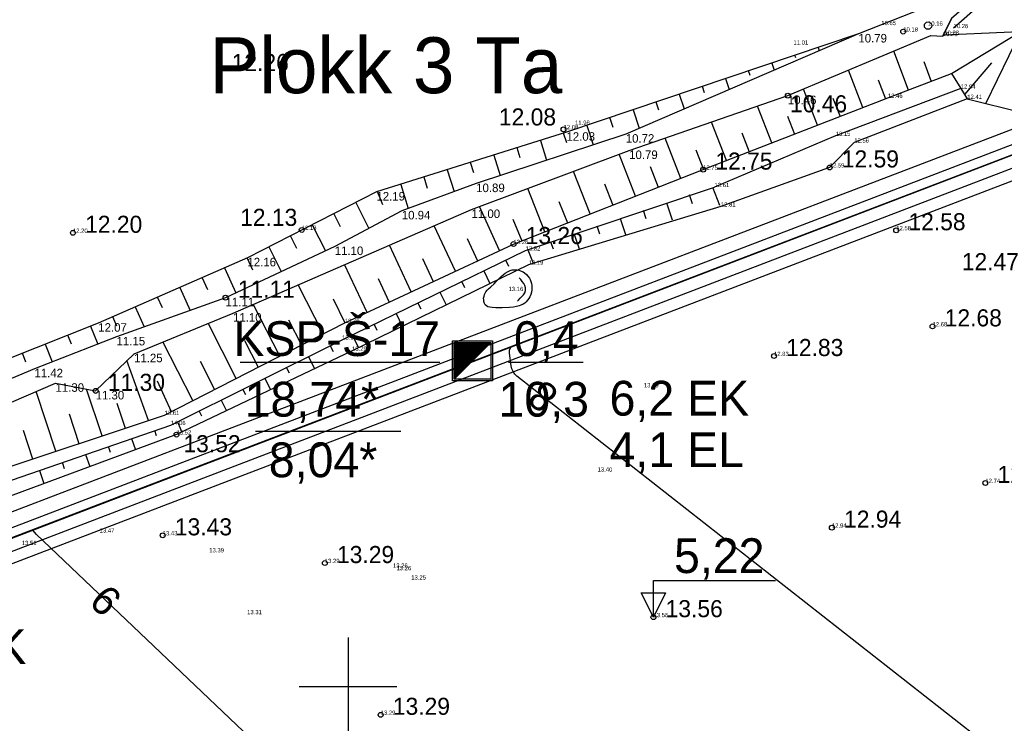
# Model space of a CAD drawing. Extents: x 433497 to 434382, y 6534486 to 6534993.
# Drawn here: x 433673.1 to 433753.8, y 6534797 to 6534854.6 of the extents above; entities that cross this region are included whole.
import ezdxf

# ---------------------------------------------------------------- set-up
doc = ezdxf.new("R2010")
doc.units = 0
for name, color, linetype in [('Default', 7, 'Continuous'), ('GEOLPUNKT', 7, 'Continuous'), ('jääkpaksus', 7, 'Continuous'), ('kataster', 7, 'Continuous'), ('KORGUS-EH2000', 7, 'Continuous'), ('Lamami horisontaal', 7, 'Continuous'), ('MOOTKORG-EH2000', 7, 'Continuous'), ('PIIR', 7, 'Continuous'), ('RELJEEF', 7, 'Continuous'), ('VEEKOGU', 7, 'Continuous'), ('VORK', 7, 'Continuous')]:
    doc.layers.add(name, color=color, linetype=linetype)

msp = doc.modelspace()

# ---------------------------------------------------------------- linework, layer by layer
at = {"layer": 'Default'}
msp.add_lwpolyline([(433617.12, 6534791.025), (433632.75, 6534606.045), (434137.38, 6534796.515), (434127.69, 6534855.6), (433968.21, 6534911.925), (433942.38, 6534904.035), (433920.99, 6534907.275)], close=True, dxfattribs=at)
msp.add_lwpolyline([(433617.12, 6534791.025), (433632.75, 6534606.045), (434137.38, 6534796.515), (434127.69, 6534855.6), (433968.21, 6534911.925), (433942.38, 6534904.035), (433920.99, 6534907.275)], close=True, dxfattribs=at)
msp.add_lwpolyline([(433617.12, 6534791.025), (433632.75, 6534606.045), (434137.38, 6534796.515), (434127.69, 6534855.6), (433968.21, 6534911.925), (433942.38, 6534904.035), (433920.99, 6534907.275)], close=True, dxfattribs=at)
at = {"layer": 'GEOLPUNKT'}
for p, q in [((433708.715, 6534825.184), (433711.715, 6534828.184)), ((433708.715, 6534825.215), (433711.685, 6534828.184)), ((433708.715, 6534825.285), (433711.614, 6534828.184)), ((433708.715, 6534825.356), (433711.543, 6534828.184)), ((433708.715, 6534825.427), (433711.472, 6534828.184)), ((433708.715, 6534825.497), (433711.402, 6534828.184)), ((433708.715, 6534825.568), (433711.331, 6534828.184)), ((433708.715, 6534825.639), (433711.26, 6534828.184)), ((433708.715, 6534825.71), (433711.19, 6534828.184)), ((433708.715, 6534825.78), (433711.119, 6534828.184)), ((433708.715, 6534825.851), (433711.048, 6534828.184)), ((433708.715, 6534825.922), (433710.977, 6534828.184)), ((433708.715, 6534825.992), (433710.907, 6534828.184)), ((433708.715, 6534826.063), (433710.836, 6534828.184)), ((433708.715, 6534826.134), (433710.765, 6534828.184)), ((433708.715, 6534826.205), (433710.695, 6534828.184)), ((433708.715, 6534826.275), (433710.624, 6534828.184)), ((433708.715, 6534826.346), (433710.553, 6534828.184)), ((433708.715, 6534826.417), (433710.482, 6534828.184)), ((433708.715, 6534826.487), (433710.412, 6534828.184)), ((433708.715, 6534826.558), (433710.341, 6534828.184)), ((433708.715, 6534826.629), (433710.27, 6534828.184)), ((433708.715, 6534826.699), (433710.2, 6534828.184)), ((433708.715, 6534826.77), (433710.129, 6534828.184)), ((433708.715, 6534826.841), (433710.058, 6534828.184)), ((433708.715, 6534826.912), (433709.987, 6534828.184)), ((433708.715, 6534826.982), (433709.917, 6534828.184)), ((433708.715, 6534827.053), (433709.846, 6534828.184)), ((433708.715, 6534827.124), (433709.775, 6534828.184)), ((433708.715, 6534827.194), (433709.705, 6534828.184)), ((433708.715, 6534827.265), (433709.634, 6534828.184)), ((433708.715, 6534827.336), (433709.563, 6534828.184)), ((433708.715, 6534827.407), (433709.493, 6534828.184)), ((433708.715, 6534827.477), (433709.422, 6534828.184)), ((433708.715, 6534827.548), (433709.351, 6534828.184)), ((433708.715, 6534827.619), (433709.28, 6534828.184)), ((433708.715, 6534827.689), (433709.21, 6534828.184)), ((433708.715, 6534827.76), (433709.139, 6534828.184)), ((433708.715, 6534827.831), (433709.068, 6534828.184)), ((433708.715, 6534827.902), (433708.998, 6534828.184)), ((433708.715, 6534827.972), (433708.927, 6534828.184)), ((433708.715, 6534828.043), (433708.856, 6534828.184)), ((433708.715, 6534828.114), (433708.785, 6534828.184)), ((433710.215, 6534826.684), (433710.215, 6534826.684))]:
    msp.add_line(p, q, dxfattribs=at)
for points in [[(433708.574, 6534828.325), (433711.856, 6534828.325), (433711.856, 6534825.043), (433708.574, 6534825.043)], [(433708.715, 6534828.184), (433711.715, 6534828.184), (433711.715, 6534825.184), (433708.715, 6534825.184)]]:
    msp.add_lwpolyline(points, close=True, dxfattribs=at)
for points in [[(433691.153, 6534826.576), (433707.537, 6534826.576)], [(433713.145, 6534826.576), (433719.273, 6534826.576)], [(433692.424, 6534820.922), (433704.34, 6534820.922)]]:
    msp.add_lwpolyline(points, dxfattribs=at)
at = {"layer": 'jääkpaksus'}
msp.add_lwpolyline([(433725.041, 6534805.672), (433725.041, 6534808.672), (433735.041, 6534808.672)], dxfattribs=at)
msp.add_lwpolyline([(433725.041, 6534805.672), (433724.041, 6534807.672), (433726.041, 6534807.672)], close=True, dxfattribs=at)
at = {"layer": 'kataster'}
msp.add_lwpolyline([(433617.102, 6534791.002), (433632.769, 6534606.029), (434137.446, 6534796.469), (434127.827, 6534855.589), (433950.026, 6534918.39)], close=True, dxfattribs=at)
at = {"layer": 'KORGUS-EH2000'}
for centre in [(433745.521, 6534853.656), (433689.463, 6534850.426), (433736.064, 6534848.408), (433717.672, 6534845.652), (433729.115, 6534842.346), (433739.486, 6534842.522), (433677.448, 6534837.168), (433696.207, 6534837.405), (433744.947, 6534837.376), (433713.567, 6534836.247), (433689.963, 6534831.852), (433747.922, 6534829.5), (433734.925, 6534827.071), (433679.31, 6534824.215), (433685.944, 6534820.634), (433752.256, 6534816.67), (433739.668, 6534813.008), (433684.807, 6534812.377), (433698.098, 6534810.108), (433725.041, 6534805.672), (433702.678, 6534797.672)]:
    msp.add_circle(centre, 0.2, dxfattribs=at)
at = {"layer": 'Lamami horisontaal'}
for points in [[(433769.589, 6534781.709), (433713.855, 6534825.424), (433713.67, 6534825.598), (433713.529, 6534825.797), (433713.431, 6534826.021), (433713.376, 6534826.269), (433713.244, 6534827.311), (433713.245, 6534827.553), (433713.313, 6534827.756), (433713.37, 6534827.825)], [(433754.697, 6534740.707), (433751.342, 6534742.853), (433736.994, 6534754.107), (433733.554, 6534756.872), (433730.182, 6534759.718), (433726.879, 6534762.643), (433723.645, 6534765.648), (433674.46, 6534812.454), (433674.172, 6534812.816)]]:
    msp.add_lwpolyline(points, dxfattribs=at)
at = {"layer": 'PIIR'}
for points in [[(433632.021, 6534604.835), (434138.248, 6534795.936), (434128.468, 6534856.135), (433968.226, 6534912.818), (433942.33, 6534904.85), (433920.952, 6534908.165), (433616.327, 6534791.524), (433632.021, 6534604.835)], [(433632.732, 6534605.959), (434137.353, 6534796.454), (434127.754, 6534855.539), (433968.208, 6534911.976), (433942.39, 6534904.031), (433921.04, 6534907.341), (433617.174, 6534790.992), (433632.732, 6534605.959)], [(433616.435, 6534792.923), (433775.118, 6534853.561)]]:
    msp.add_lwpolyline(points, dxfattribs=at)
for points in [[(433618.234, 6534790.327), (433921.149, 6534906.313), (433942.464, 6534903.008), (433968.187, 6534910.923), (434126.862, 6534854.794), (434136.235, 6534797.101), (433633.617, 6534607.362)], [(433619.24, 6534789.695), (433634.52, 6534608.851), (434135.141, 6534797.808), (434125.908, 6534854.108), (433968.165, 6534909.82), (433942.53, 6534901.99), (433921.212, 6534905.219)], [(433619.24, 6534789.695), (433634.52, 6534608.851), (434135.141, 6534797.808), (434125.908, 6534854.108), (433968.165, 6534909.82), (433942.53, 6534901.99), (433921.212, 6534905.219)]]:
    msp.add_lwpolyline(points, close=True, dxfattribs=at)
at = {"layer": 'RELJEEF'}
for p, q in [((433744.177, 6534854.381), (433744.177, 6534854.381)), ((433740.448, 6534852.932), (433740.428, 6534852.99)), ((433742.315, 6534853.651), (433742.315, 6534853.651)), ((433749.491, 6534850.215), (433755.149, 6534853.676)), ((433752.285, 6534847.764), (433755.149, 6534853.676)), ((433738.533, 6534852.352), (433738.624, 6534852.08)), ((433736.709, 6534851.5), (433736.637, 6534851.714)), ((433745.944, 6534848.858), (433744.742, 6534852.05)), ((433734.742, 6534851.076), (433734.938, 6534850.492)), ((433747.203, 6534851.193), (433747.816, 6534849.561)), ((433752.763, 6534851.09), (433750.537, 6534848.511)), ((433730.951, 6534849.8), (433731.252, 6534848.905)), ((433732.971, 6534850.068), (433732.846, 6534850.438)), ((433742.208, 6534847.428), (433741.02, 6534850.488)), ((433729.232, 6534848.637), (433729.055, 6534849.162)), ((433743.476, 6534849.71), (433744.072, 6534848.152)), ((433727.16, 6534848.524), (433727.566, 6534847.318)), ((433738.479, 6534845.981), (433737.331, 6534848.94)), ((433739.759, 6534848.209), (433740.343, 6534846.705)), ((433725.493, 6534847.205), (433725.264, 6534847.886)), ((433734.75, 6534844.533), (433733.579, 6534847.551)), ((433721.744, 6534845.807), (433721.473, 6534846.61)), ((433723.369, 6534847.248), (433723.879, 6534845.73)), ((433736.043, 6534846.73), (433736.615, 6534845.257)), ((433719.578, 6534845.972), (433720.113, 6534844.375)), ((433731.021, 6534843.086), (433729.795, 6534846.245)), ((433717.939, 6534844.541), (433717.681, 6534845.339)), ((433727.295, 6534841.632), (433725.999, 6534844.935)), ((433732.286, 6534845.354), (433732.886, 6534843.81)), ((433714.125, 6534843.312), (433713.865, 6534844.14)), ((433715.773, 6534844.739), (433716.284, 6534843.111)), ((433711.957, 6534843.54), (433712.486, 6534841.857)), ((433723.571, 6534840.171), (433722.223, 6534843.608)), ((433728.527, 6534843.976), (433729.157, 6534842.362)), ((433710.317, 6534842.085), (433710.049, 6534842.94)), ((433724.77, 6534842.592), (433725.433, 6534840.902)), ((433706.529, 6534840.797), (433706.233, 6534841.741)), ((433708.141, 6534842.341), (433708.706, 6534840.542)), ((433719.847, 6534838.711), (433718.476, 6534842.206)), ((433704.325, 6534841.141), (433704.946, 6534839.163)), ((433721.029, 6534841.174), (433721.709, 6534839.441)), ((433729.895, 6534840.912), (433730.45, 6534839.429)), ((433702.855, 6534839.457), (433702.417, 6534840.542)), ((433716.124, 6534837.25), (433714.73, 6534840.803)), ((433728.248, 6534839.542), (433728.001, 6534840.27)), ((433700.629, 6534839.647), (433701.701, 6534837.527)), ((433712.431, 6534835.716), (433710.794, 6534839.33)), ((433717.294, 6534839.742), (433717.985, 6534837.98)), ((433726.107, 6534839.627), (433726.585, 6534838.219)), ((433699.395, 6534837.666), (433698.848, 6534838.739)), ((433724.444, 6534838.305), (433724.213, 6534838.985)), ((433697.066, 6534837.83), (433698.157, 6534835.691)), ((433708.807, 6534834.023), (433707.066, 6534837.751)), ((433713.523, 6534838.297), (433714.262, 6534836.52)), ((433720.639, 6534837.068), (433720.425, 6534837.7)), ((433722.319, 6534838.342), (433722.764, 6534837.031)), ((433695.815, 6534835.882), (433695.284, 6534836.921)), ((433718.531, 6534837.057), (433718.943, 6534835.843)), ((433705.183, 6534832.33), (433703.395, 6534836.156)), ((433709.76, 6534836.709), (433710.619, 6534834.87)), ((433716.835, 6534835.832), (433716.637, 6534836.415)), ((433693.503, 6534836.012), (433694.532, 6534833.993)), ((433714.743, 6534835.772), (433715.186, 6534834.674)), ((433692.19, 6534834.111), (433691.72, 6534835.106)), ((433701.559, 6534830.637), (433699.725, 6534834.562)), ((433706.113, 6534835.065), (433706.995, 6534833.176)), ((433713.182, 6534834.403), (433712.935, 6534834.922)), ((433689.888, 6534834.303), (433690.792, 6534832.24)), ((433711.135, 6534834.048), (433711.639, 6534833.012)), ((433688.498, 6534832.493), (433688.056, 6534833.501)), ((433697.966, 6534828.881), (433695.911, 6534832.906)), ((433702.466, 6534833.421), (433703.371, 6534831.483)), ((433709.588, 6534832.655), (433709.336, 6534833.175)), ((433686.224, 6534832.698), (433687.053, 6534830.807)), ((433707.537, 6534832.302), (433708.043, 6534831.259)), ((433684.779, 6534831.013), (433684.392, 6534831.896)), ((433694.403, 6534827.062), (433692.234, 6534831.309)), ((433698.784, 6534831.763), (433699.747, 6534829.79)), ((433705.991, 6534830.906), (433705.738, 6534831.428)), ((433682.56, 6534831.094), (433683.279, 6534829.452)), ((433703.938, 6534830.555), (433704.447, 6534829.507)), ((433681.056, 6534829.531), (433680.728, 6534830.291)), ((433690.841, 6534825.243), (433688.538, 6534829.753)), ((433695.129, 6534830.039), (433696.185, 6534827.971)), ((433702.394, 6534829.156), (433702.139, 6534829.682)), ((433677.318, 6534828.044), (433677.029, 6534828.772)), ((433678.887, 6534829.511), (433679.488, 6534828.046)), ((433700.34, 6534828.808), (433700.854, 6534827.756)), ((433675.17, 6534828.034), (433675.743, 6534826.591)), ((433687.279, 6534823.424), (433684.824, 6534828.231)), ((433691.508, 6534828.333), (433692.622, 6534826.152)), ((433673.597, 6534826.575), (433673.311, 6534827.295)), ((433698.801, 6534827.409), (433698.546, 6534827.925)), ((433683.635, 6534821.799), (433681.881, 6534826.703)), ((433687.87, 6534826.663), (433689.06, 6534824.333)), ((433696.756, 6534827.033), (433697.254, 6534826.032)), ((433695.207, 6534825.656), (433694.965, 6534826.141)), ((433684.368, 6534825.048), (433685.497, 6534822.514)), ((433693.175, 6534825.249), (433693.644, 6534824.309)), ((433676.042, 6534819.277), (433674.423, 6534824.154)), ((433679.839, 6534820.538), (433678.571, 6534824.356)), ((433691.612, 6534823.902), (433691.385, 6534824.357)), ((433681.059, 6534823.21), (433681.737, 6534821.169)), ((433689.595, 6534823.465), (433690.033, 6534822.586)), ((433677.131, 6534822.346), (433677.941, 6534819.908)), ((433688.017, 6534822.149), (433687.805, 6534822.573)), ((433686.015, 6534821.682), (433686.385, 6534820.845)), ((433673.362, 6534821.004), (433674.144, 6534818.647)), ((433684.313, 6534820.525), (433684.154, 6534820.958)), ((433682.263, 6534820.306), (433682.578, 6534819.393)), ((433680.537, 6534819.178), (433680.372, 6534819.655)), ((433676.768, 6534817.835), (433676.59, 6534818.353)), ((433678.481, 6534819.004), (433678.824, 6534818.01)), ((433674.699, 6534817.701), (433675.07, 6534816.626))]:
    msp.add_line(p, q, dxfattribs=at)
for points in [[(433749.058, 6534856.332), (433741.841, 6534853.465), (433717.91, 6534845.411), (433702.328, 6534840.514), (433691.755, 6534835.121), (433679.525, 6534829.764), (433651.528, 6534818.64), (433637.327, 6534811.851), (433630.595, 6534812.126), (433622.045, 6534814.376), (433614.685, 6534815.117), (433605.841, 6534812.999), (433591.428, 6534809.544), (433575.413, 6534803.952), (433570.231, 6534802.507)], [(433748.878, 6534853.388), (433758.098, 6534853.811), (433758.55, 6534853.739), (433761.921, 6534850.308), (433764.481, 6534836.032), (433767.075, 6534825.983), (433774.182, 6534815.18), (433782.466, 6534821.229), (433788.255, 6534818.706), (433796.133, 6534810.618), (433803.931, 6534804.97), (433804.761, 6534801.339), (433805.697, 6534793.531), (433812.468, 6534796.545), (433823.626, 6534801.375)], [(433641.312, 6534803.133), (433641.312, 6534803.133), (433655.696, 6534810.311), (433657.191, 6534811.686), (433670.478, 6534817.429), (433684.961, 6534822.24), (433699.73, 6534829.782), (433713.567, 6534836.247), (433729.115, 6534842.346), (433744.26, 6534848.225), (433749.491, 6534850.215), (433750.242, 6534848.987), (433750.768, 6534848.139), (433755.391, 6534846.995), (433755.787, 6534835.054), (433756.5, 6534822.235), (433759.761, 6534816.596), (433770.429, 6534806.118), (433779.564, 6534811.62), (433786.937, 6534803.288), (433796.573, 6534795.821), (433800.033, 6534788.924)], [(433750.242, 6534848.987), (433739.98, 6534845.11), (433730.046, 6534840.914)], [(433750.768, 6534848.139), (433741.507, 6534844.56), (433739.486, 6534842.522), (433730.566, 6534839.32)], [(433655.696, 6534810.311), (433670.889, 6534816.389), (433685.476, 6534821.413), (433699.519, 6534828.41), (433714.557, 6534835.709), (433730.046, 6534840.914)], [(433730.566, 6534839.32), (433714.807, 6534834.556), (433700.329, 6534827.5), (433685.944, 6534820.634), (433670.062, 6534814.781), (433657.216, 6534808.578), (433654.486, 6534807.171), (433651.269, 6534805.154), (433641.651, 6534802.36), (433641.312, 6534803.133)], [(433711.113, 6534831.824), (433711.151, 6534831.973), (433711.194, 6534832.104), (433711.238, 6534832.211), (433711.3, 6534832.325), (433711.402, 6534832.466), (433711.526, 6534832.592), (433711.697, 6534832.746), (433711.972, 6534832.997), (433712.152, 6534833.176), (433712.407, 6534833.44), (433712.552, 6534833.582), (433712.746, 6534833.75), (433712.896, 6534833.86), (433713.073, 6534833.967), (433713.291, 6534834.068), (433713.47, 6534834.122), (433713.662, 6534834.145), (433713.829, 6534834.137), (433714.002, 6534834.105), (433714.155, 6534834.056), (433714.355, 6534833.962), (433714.478, 6534833.884), (433714.643, 6534833.748), (433714.755, 6534833.627), (433714.87, 6534833.463), (433714.937, 6534833.338), (433715.001, 6534833.177), (433715.046, 6534833.009), (433715.072, 6534832.846), (433715.081, 6534832.678), (433715.074, 6534832.494), (433715.046, 6534832.303), (433714.998, 6534832.124), (433714.919, 6534831.936), (433714.834, 6534831.787), (433714.728, 6534831.641), (433714.608, 6534831.512), (433714.497, 6534831.415), (433714.351, 6534831.316), (433714.179, 6534831.229), (433714.031, 6534831.175), (433713.826, 6534831.123), (433713.555, 6534831.083), (433713.241, 6534831.054), (433712.646, 6534831.028), (433712.12, 6534831.026), (433711.808, 6534831.038), (433711.618, 6534831.064), (433711.471, 6534831.109), (433711.354, 6534831.173), (433711.258, 6534831.263), (433711.192, 6534831.376), (433711.146, 6534831.53), (433711.123, 6534831.679), (433711.113, 6534831.824)], [(433713.883, 6534831.564), (433713.968, 6534831.654), (433714.105, 6534831.8), (433714.241, 6534831.947), (433714.376, 6534832.095), (433714.489, 6534832.258), (433714.539, 6534832.451), (433714.54, 6534832.651), (433714.498, 6534832.846), (433714.413, 6534833.026), (433714.287, 6534833.182), (433714.156, 6534833.332), (433714.024, 6534833.483)], [(433673.115, 6534820.287), (433673.115, 6534820.287), (433673.115, 6534820.287), (433673.115, 6534820.287), (433673.115, 6534820.287)]]:
    msp.add_lwpolyline(points, dxfattribs=at)
at = {"layer": 'VEEKOGU'}
msp.add_line((433748.765, 6534853.283), (433749.479, 6534854.726), dxfattribs=at)
for points in [[(433917.357, 6534901.473), (433910.646, 6534903.91), (433905.733, 6534906.185), (433897.201, 6534904.664), (433864.652, 6534892.255), (433840.997, 6534882.39), (433822.758, 6534877.106), (433813.338, 6534872.69), (433806.812, 6534870.137), (433792.733, 6534866.126), (433778.163, 6534862.151), (433760.314, 6534861.045), (433757.652, 6534861.824), (433749.479, 6534854.726), (433748.765, 6534853.283)], [(433822.217, 6534876.48), (433821.93, 6534876.376), (433813.446, 6534872.233), (433806.595, 6534869.831), (433792.716, 6534865.968), (433778.125, 6534861.85), (433760.219, 6534860.83), (433757.827, 6534861.154), (433749.641, 6534853.939)], [(433749.058, 6534856.332), (433741.841, 6534853.465), (433722.771, 6534845.253), (433710.509, 6534841.204), (433704.412, 6534838.967), (433698.912, 6534836.045), (433689.963, 6534831.852), (433681.025, 6534828.643), (433674.289, 6534826.026), (433651.647, 6534816.525), (433637.528, 6534810.175), (433630.797, 6534811.068), (433623.412, 6534812.9), (433613.311, 6534813.674), (433591.338, 6534808.449), (433572.407, 6534802.271)], [(433572.968, 6534800.411), (433591.847, 6534807.886), (433613.835, 6534811.689), (433622.814, 6534811.64), (433631.731, 6534808.602), (433638.345, 6534808.16), (433643.538, 6534810.243), (433652.755, 6534814.828), (433676.018, 6534824.841), (433679.31, 6534824.215), (433682.459, 6534827.262), (433690.574, 6534830.588), (433710.129, 6534839.081), (433723.05, 6534843.918), (433736.064, 6534848.408), (433747.792, 6534853.33), (433748.765, 6534853.283)]]:
    msp.add_lwpolyline(points, dxfattribs=at)
msp.add_circle((433747.554, 6534854.144), 0.3, dxfattribs=at)
at = {"layer": 'VORK'}
for p, q in [((433700, 6534804), (433700, 6534796)), ((433696, 6534800), (433704, 6534800))]:
    msp.add_line(p, q, dxfattribs=at)

# ---------------------------------------------------------------- texts
at = {"layer": 'GEOLPUNKT'}
for s, p in [('KSP-Š-17', (433690.602, 6534827.072)), ('0,4', (433713.61, 6534827.072)), ('18,74*', (433691.528, 6534822.107)), ('10,3', (433712.339, 6534822.107)), ('6,2 EK', (433721.442, 6534822.19)), ('4,1 EL', (433721.442, 6534817.97)), ('8,04*', (433693.506, 6534817.142)), ('4,5 EK', (433662.192, 6534801.833))]:
    msp.add_text(s, height=2.85, dxfattribs=at).set_placement(p)
at = {"layer": 'jääkpaksus'}
msp.add_text(' 5,22', height=2.85, rotation=360, dxfattribs=at).set_placement((433725.67, 6534809.289))
at = {"layer": 'KORGUS-EH2000'}
for s, p in [('12.26', (433690.463, 6534850.426)), ('10.46', (433736.235, 6534847.04)), ('12.08', (433712.372, 6534845.964)), ('12.75', (433730.115, 6534842.346)), ('12.59', (433740.486, 6534842.522)), ('12.20', (433678.448, 6534837.168)), ('12.13', (433691.156, 6534837.737)), ('12.58', (433745.947, 6534837.376)), ('13.26', (433714.567, 6534836.247)), ('12.47', (433750.321, 6534834.106)), ('11.11', (433690.963, 6534831.852)), ('12.68', (433748.922, 6534829.5)), ('12.83', (433735.925, 6534827.071)), ('11.30', (433680.31, 6534824.215)), ('13.52', (433686.509, 6534819.188)), ('12.74', (433753.256, 6534816.67)), ('12.94', (433740.668, 6534813.008)), ('13.43', (433685.807, 6534812.377)), ('13.29', (433699.098, 6534810.108)), ('13.56', (433726.041, 6534805.672)), ('13.29', (433703.678, 6534797.672))]:
    msp.add_text(s, height=1.4, dxfattribs=at).set_placement(p)
at = {"layer": 'Lamami horisontaal'}
for s, rotation, p in [('8', 141.89127, (433717.422, 6534824.151)), ('9', 136.41945, (433681.621, 6534807.296))]:
    msp.add_text(s, height=2.4, rotation=rotation, dxfattribs=at).set_placement(p)
at = {"layer": 'MOOTKORG-EH2000'}
for s, height, p in [('10.65', 0.35, (433743.721, 6534854.186)), ('10.18', 0.35, (433745.521, 6534853.656)), ('10.16', 0.35, (433747.554, 6534854.144)), ('10.26', 0.35, (433749.641, 6534853.939)), ('10.79', 0.7, (433741.841, 6534852.765)), ('10.23', 0.35, (433748.765, 6534853.283)), ('10.23', 0.35, (433748.878, 6534853.388)), ('11.01', 0.35, (433736.521, 6534852.594)), ('12.26', 0.35, (433689.463, 6534850.426)), ('12.94', 0.35, (433750.242, 6534848.987)), ('10.46', 0.7, (433736.064, 6534847.708)), ('12.46', 0.35, (433744.26, 6534848.225)), ('12.41', 0.35, (433750.768, 6534848.139)), ('12.08', 0.35, (433717.672, 6534845.652)), ('11.98', 0.35, (433718.612, 6534846.019)), ('12.03', 0.7, (433717.91, 6534844.711)), ('10.72', 0.7, (433722.771, 6534844.553)), ('13.15', 0.35, (433739.98, 6534845.11)), ('12.56', 0.35, (433741.507, 6534844.56)), ('10.79', 0.7, (433723.05, 6534843.218)), ('12.75', 0.35, (433729.115, 6534842.346)), ('12.59', 0.35, (433739.486, 6534842.522)), ('10.89', 0.7, (433710.509, 6534840.504)), ('13.61', 0.35, (433730.046, 6534840.914)), ('12.19', 0.7, (433702.328, 6534839.814)), ('12.81', 0.35, (433730.566, 6534839.32)), ('10.94', 0.7, (433704.412, 6534838.267)), ('11.00', 0.7, (433710.129, 6534838.381)), ('12.13', 0.35, (433696.207, 6534837.405)), ('12.58', 0.35, (433744.947, 6534837.376)), ('12.20', 0.35, (433677.448, 6534837.168)), ('11.10', 0.7, (433698.912, 6534835.345)), ('13.26', 0.35, (433713.567, 6534836.247)), ('13.82', 0.35, (433714.557, 6534835.709)), ('12.16', 0.7, (433691.755, 6534834.421)), ('13.19', 0.35, (433714.807, 6534834.556)), ('13.16', 0.35, (433713.163, 6534832.394)), ('11.11', 0.7, (433689.963, 6534831.152)), ('11.10', 0.7, (433690.574, 6534829.888)), ('12.07', 0.7, (433679.525, 6534829.064)), ('13.36', 0.35, (433699.73, 6534829.782)), ('12.68', 0.35, (433747.922, 6534829.5)), ('11.15', 0.7, (433681.025, 6534827.943)), ('13.97', 0.35, (433699.519, 6534828.41)), ('11.25', 0.7, (433682.459, 6534826.562)), ('13.29', 0.35, (433700.329, 6534827.5)), ('12.83', 0.35, (433734.925, 6534827.071)), ('11.42', 0.7, (433674.289, 6534825.326)), ('11.30', 0.7, (433676.018, 6534824.141)), ('13.19', 0.35, (433724.256, 6534824.508)), ('11.30', 0.7, (433679.31, 6534823.515)), ('13.61', 0.35, (433684.961, 6534822.24)), ('14.06', 0.35, (433685.476, 6534821.413)), ('13.52', 0.35, (433685.944, 6534820.634)), ('13.40', 0.35, (433720.464, 6534817.605)), ('12.74', 0.35, (433752.256, 6534816.67)), ('13.47', 0.35, (433679.644, 6534812.612)), ('13.43', 0.35, (433684.807, 6534812.377)), ('12.94', 0.35, (433739.668, 6534813.008)), ('13.51', 0.35, (433673.259, 6534811.583)), ('13.39', 0.35, (433688.622, 6534810.987)), ('13.29', 0.35, (433698.098, 6534810.108)), ('13.26', 0.35, (433703.69, 6534809.726)), ('13.26', 0.35, (433703.98, 6534809.521)), ('13.25', 0.35, (433705.184, 6534808.758)), ('13.31', 0.35, (433691.731, 6534805.917)), ('13.56', 0.35, (433725.041, 6534805.672)), ('13.29', 0.35, (433702.678, 6534797.672))]:
    msp.add_text(s, height=height, dxfattribs=at).set_placement(p)
at = {"layer": 'PIIR'}
msp.add_text('Plokk 3 Ta', height=4.58, dxfattribs=at).set_placement((433688.643, 6534848.608))

doc.saveas('drawing.dxf')
